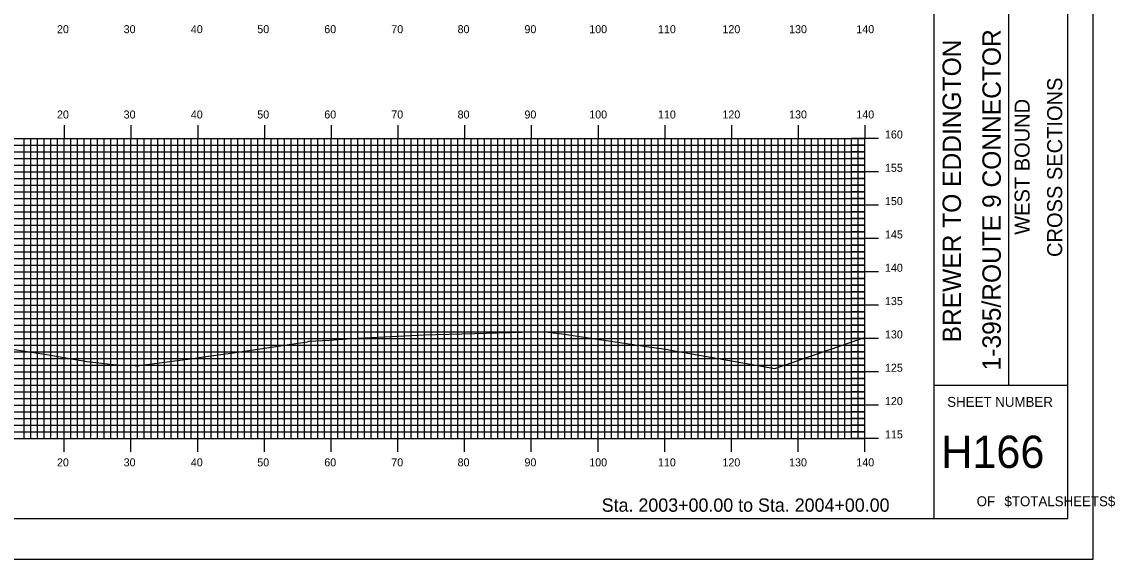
# Model space of a CAD drawing. Extents: x 851533 to 851876, y 366605 to 366825.
# Drawn here: x 851712.1 to 851875.9, y 366604.9 to 366685.6 of the extents above; entities that cross this region are included whole.
import ezdxf

# ---------------------------------------------------------------- set-up
doc = ezdxf.new("R2010")
doc.units = 0
for name, color, linetype in [('BORDER', 7, 'Continuous'), ('H_V ANNOTATION', 7, 'Continuous'), ('M_Roadway_Centerline', 7, 'Continuous'), ('MAJOR', 7, 'Continuous'), ('MINOR', 7, 'Continuous'), ('PLOT BOUNDARY', 7, 'Continuous'), ('S_Roadway_Centerline', 7, 'Continuous')]:
    doc.layers.add(name, color=color, linetype=linetype)

msp = doc.modelspace()

# ---------------------------------------------------------------- linework, layer by layer
at = {"layer": 'BORDER'}
for p, q in [((851848.85, 366611.06), (851848.85, 366821.06)), ((851860.03, 366631.06), (851860.03, 366701.06)), ((851848.85, 366631.06), (851868.85, 366631.06))]:
    msp.add_line(p, q, dxfattribs=at)
msp.add_lwpolyline([(851548.85, 366611.06), (851868.85, 366611.06), (851868.85, 366821.06), (851548.85, 366821.06)], close=True, dxfattribs=at)
at = {"layer": 'MAJOR'}
for p, q in [((851718.45, 366670.06), (851718.45, 366668.06)), ((851728.45, 366670.06), (851728.45, 366668.06)), ((851738.45, 366670.06), (851738.45, 366668.06)), ((851748.45, 366670.06), (851748.45, 366668.06)), ((851758.45, 366670.06), (851758.45, 366668.06)), ((851768.45, 366670.06), (851768.45, 366668.06)), ((851778.45, 366670.06), (851778.45, 366668.06)), ((851788.45, 366670.06), (851788.45, 366668.06)), ((851798.45, 366670.06), (851798.45, 366668.06)), ((851808.45, 366670.06), (851808.45, 366668.06)), ((851818.45, 366670.06), (851818.45, 366668.06)), ((851828.45, 366670.06), (851828.45, 366668.06)), ((851838.45, 366670.06), (851838.45, 366668.06)), ((851558.45, 366668.06), (851838.45, 366668.06)), ((851558.45, 366668.06), (851838.45, 366668.06)), ((851718.45, 366623.06), (851718.45, 366668.06)), ((851728.45, 366623.06), (851728.45, 366668.06)), ((851738.45, 366623.06), (851738.45, 366668.06)), ((851748.45, 366623.06), (851748.45, 366668.06)), ((851758.45, 366623.06), (851758.45, 366668.06)), ((851768.45, 366623.06), (851768.45, 366668.06)), ((851778.45, 366623.06), (851778.45, 366668.06)), ((851788.45, 366623.06), (851788.45, 366668.06)), ((851798.45, 366623.06), (851798.45, 366668.06)), ((851808.45, 366623.06), (851808.45, 366668.06)), ((851818.45, 366623.06), (851818.45, 366668.06)), ((851828.45, 366623.06), (851828.45, 366668.06)), ((851840.46, 366668.06), (851836.45, 366668.06)), ((851838.45, 366623.06), (851838.45, 366668.06)), ((851838.45, 366623.06), (851838.45, 366668.06)), ((851558.45, 366663.06), (851838.45, 366663.06)), ((851840.46, 366663.06), (851836.45, 366663.06)), ((851558.45, 366658.06), (851838.45, 366658.06)), ((851840.46, 366658.06), (851836.45, 366658.06)), ((851558.45, 366653.06), (851838.45, 366653.06)), ((851840.46, 366653.06), (851836.45, 366653.06)), ((851558.45, 366648.06), (851838.45, 366648.06)), ((851840.46, 366648.06), (851836.45, 366648.06)), ((851558.45, 366643.06), (851838.45, 366643.06)), ((851840.46, 366643.06), (851836.45, 366643.06)), ((851558.45, 366638.06), (851838.45, 366638.06)), ((851840.46, 366638.06), (851836.45, 366638.06)), ((851558.45, 366633.06), (851838.45, 366633.06)), ((851840.46, 366633.06), (851836.45, 366633.06)), ((851558.45, 366628.06), (851838.45, 366628.06)), ((851840.46, 366628.06), (851836.45, 366628.06)), ((851558.45, 366623.06), (851838.45, 366623.06)), ((851558.45, 366623.06), (851838.45, 366623.06)), ((851718.45, 366621.05), (851718.45, 366623.06)), ((851728.45, 366621.05), (851728.45, 366623.06)), ((851738.45, 366621.05), (851738.45, 366623.06)), ((851748.45, 366621.05), (851748.45, 366623.06)), ((851758.45, 366621.05), (851758.45, 366623.06)), ((851768.45, 366621.05), (851768.45, 366623.06)), ((851778.45, 366621.05), (851778.45, 366623.06)), ((851788.45, 366621.05), (851788.45, 366623.06)), ((851798.45, 366621.05), (851798.45, 366623.06)), ((851808.45, 366621.05), (851808.45, 366623.06)), ((851818.45, 366621.05), (851818.45, 366623.06)), ((851828.45, 366621.05), (851828.45, 366623.06)), ((851840.46, 366623.06), (851836.45, 366623.06)), ((851838.45, 366621.05), (851838.45, 366623.06))]:
    msp.add_line(p, q, dxfattribs=at)
at = {"layer": 'MINOR'}
for p, q in [((851558.45, 366667.06), (851838.45, 366667.06)), ((851712.45, 366623.06), (851712.45, 366668.06)), ((851713.45, 366623.06), (851713.45, 366668.06)), ((851714.45, 366623.06), (851714.45, 366668.06)), ((851715.45, 366623.06), (851715.45, 366668.06)), ((851716.45, 366623.06), (851716.45, 366668.06)), ((851717.45, 366623.06), (851717.45, 366668.06)), ((851719.45, 366623.06), (851719.45, 366668.06)), ((851720.45, 366623.06), (851720.45, 366668.06)), ((851721.45, 366623.06), (851721.45, 366668.06)), ((851722.45, 366623.06), (851722.45, 366668.06)), ((851723.45, 366623.06), (851723.45, 366668.06)), ((851724.45, 366623.06), (851724.45, 366668.06)), ((851725.45, 366623.06), (851725.45, 366668.06)), ((851726.45, 366623.06), (851726.45, 366668.06)), ((851727.45, 366623.06), (851727.45, 366668.06)), ((851729.45, 366623.06), (851729.45, 366668.06)), ((851730.45, 366623.06), (851730.45, 366668.06)), ((851731.45, 366623.06), (851731.45, 366668.06)), ((851732.45, 366623.06), (851732.45, 366668.06)), ((851733.45, 366623.06), (851733.45, 366668.06)), ((851734.45, 366623.06), (851734.45, 366668.06)), ((851735.45, 366623.06), (851735.45, 366668.06)), ((851736.45, 366623.06), (851736.45, 366668.06)), ((851737.45, 366623.06), (851737.45, 366668.06)), ((851739.45, 366623.06), (851739.45, 366668.06)), ((851740.45, 366623.06), (851740.45, 366668.06)), ((851741.45, 366623.06), (851741.45, 366668.06)), ((851742.45, 366623.06), (851742.45, 366668.06)), ((851743.45, 366623.06), (851743.45, 366668.06)), ((851744.45, 366623.06), (851744.45, 366668.06)), ((851745.45, 366623.06), (851745.45, 366668.06)), ((851746.45, 366623.06), (851746.45, 366668.06)), ((851747.45, 366623.06), (851747.45, 366668.06)), ((851749.45, 366623.06), (851749.45, 366668.06)), ((851750.45, 366623.06), (851750.45, 366668.06)), ((851751.45, 366623.06), (851751.45, 366668.06)), ((851752.45, 366623.06), (851752.45, 366668.06)), ((851753.45, 366623.06), (851753.45, 366668.06)), ((851754.45, 366623.06), (851754.45, 366668.06)), ((851755.45, 366623.06), (851755.45, 366668.06)), ((851756.45, 366623.06), (851756.45, 366668.06)), ((851757.45, 366623.06), (851757.45, 366668.06)), ((851759.45, 366623.06), (851759.45, 366668.06)), ((851760.45, 366623.06), (851760.45, 366668.06)), ((851761.45, 366623.06), (851761.45, 366668.06)), ((851762.45, 366623.06), (851762.45, 366668.06)), ((851763.45, 366623.06), (851763.45, 366668.06)), ((851764.45, 366623.06), (851764.45, 366668.06)), ((851765.45, 366623.06), (851765.45, 366668.06)), ((851766.45, 366623.06), (851766.45, 366668.06)), ((851767.45, 366623.06), (851767.45, 366668.06)), ((851769.45, 366623.06), (851769.45, 366668.06)), ((851770.45, 366623.06), (851770.45, 366668.06)), ((851771.45, 366623.06), (851771.45, 366668.06)), ((851772.45, 366623.06), (851772.45, 366668.06)), ((851773.45, 366623.06), (851773.45, 366668.06)), ((851774.45, 366623.06), (851774.45, 366668.06)), ((851775.45, 366623.06), (851775.45, 366668.06)), ((851776.45, 366623.06), (851776.45, 366668.06)), ((851777.45, 366623.06), (851777.45, 366668.06)), ((851779.45, 366623.06), (851779.45, 366668.06)), ((851780.45, 366623.06), (851780.45, 366668.06)), ((851781.45, 366623.06), (851781.45, 366668.06)), ((851782.45, 366623.06), (851782.45, 366668.06)), ((851783.45, 366623.06), (851783.45, 366668.06)), ((851784.45, 366623.06), (851784.45, 366668.06)), ((851785.45, 366623.06), (851785.45, 366668.06)), ((851786.45, 366623.06), (851786.45, 366668.06)), ((851787.45, 366623.06), (851787.45, 366668.06)), ((851789.45, 366623.06), (851789.45, 366668.06)), ((851790.45, 366623.06), (851790.45, 366668.06)), ((851791.45, 366623.06), (851791.45, 366668.06)), ((851792.45, 366623.06), (851792.45, 366668.06)), ((851793.45, 366623.06), (851793.45, 366668.06)), ((851794.45, 366623.06), (851794.45, 366668.06)), ((851795.45, 366623.06), (851795.45, 366668.06)), ((851796.45, 366623.06), (851796.45, 366668.06)), ((851797.45, 366623.06), (851797.45, 366668.06)), ((851799.45, 366623.06), (851799.45, 366668.06)), ((851800.45, 366623.06), (851800.45, 366668.06)), ((851801.45, 366623.06), (851801.45, 366668.06)), ((851802.45, 366623.06), (851802.45, 366668.06)), ((851803.45, 366623.06), (851803.45, 366668.06)), ((851804.45, 366623.06), (851804.45, 366668.06)), ((851805.45, 366623.06), (851805.45, 366668.06)), ((851806.45, 366623.06), (851806.45, 366668.06)), ((851807.45, 366623.06), (851807.45, 366668.06)), ((851809.45, 366623.06), (851809.45, 366668.06)), ((851810.45, 366623.06), (851810.45, 366668.06)), ((851811.45, 366623.06), (851811.45, 366668.06)), ((851812.45, 366623.06), (851812.45, 366668.06)), ((851813.45, 366623.06), (851813.45, 366668.06)), ((851814.45, 366623.06), (851814.45, 366668.06)), ((851815.45, 366623.06), (851815.45, 366668.06)), ((851816.45, 366623.06), (851816.45, 366668.06)), ((851817.45, 366623.06), (851817.45, 366668.06)), ((851819.45, 366623.06), (851819.45, 366668.06)), ((851820.45, 366623.06), (851820.45, 366668.06)), ((851821.45, 366623.06), (851821.45, 366668.06)), ((851822.45, 366623.06), (851822.45, 366668.06)), ((851823.45, 366623.06), (851823.45, 366668.06)), ((851824.45, 366623.06), (851824.45, 366668.06)), ((851825.45, 366623.06), (851825.45, 366668.06)), ((851826.45, 366623.06), (851826.45, 366668.06)), ((851827.45, 366623.06), (851827.45, 366668.06)), ((851829.45, 366623.06), (851829.45, 366668.06)), ((851830.45, 366623.06), (851830.45, 366668.06)), ((851831.45, 366623.06), (851831.45, 366668.06)), ((851832.45, 366623.06), (851832.45, 366668.06)), ((851833.45, 366623.06), (851833.45, 366668.06)), ((851834.45, 366623.06), (851834.45, 366668.06)), ((851835.45, 366623.06), (851835.45, 366668.06)), ((851836.45, 366623.06), (851836.45, 366668.06)), ((851838.45, 366667.06), (851836.45, 366667.06)), ((851837.45, 366623.06), (851837.45, 366668.06)), ((851558.45, 366666.06), (851838.45, 366666.06)), ((851838.45, 366666.06), (851836.45, 366666.06)), ((851558.45, 366665.06), (851838.45, 366665.06)), ((851558.45, 366664.06), (851838.45, 366664.06)), ((851838.45, 366665.06), (851836.45, 366665.06)), ((851838.45, 366664.06), (851836.45, 366664.06)), ((851558.45, 366662.06), (851838.45, 366662.06)), ((851838.45, 366662.06), (851836.45, 366662.06)), ((851558.45, 366661.06), (851838.45, 366661.06)), ((851838.45, 366661.06), (851836.45, 366661.06)), ((851558.45, 366660.06), (851838.45, 366660.06)), ((851558.45, 366659.06), (851838.45, 366659.06)), ((851838.45, 366660.06), (851836.45, 366660.06)), ((851838.45, 366659.06), (851836.45, 366659.06)), ((851558.45, 366657.06), (851838.45, 366657.06)), ((851838.45, 366657.06), (851836.45, 366657.06)), ((851558.45, 366656.06), (851838.45, 366656.06)), ((851838.45, 366656.06), (851836.45, 366656.06)), ((851558.45, 366655.06), (851838.45, 366655.06)), ((851558.45, 366654.06), (851838.45, 366654.06)), ((851838.45, 366655.06), (851836.45, 366655.06)), ((851838.45, 366654.06), (851836.45, 366654.06)), ((851558.45, 366652.06), (851838.45, 366652.06)), ((851558.45, 366651.06), (851838.45, 366651.06)), ((851838.45, 366652.06), (851836.45, 366652.06)), ((851838.45, 366651.06), (851836.45, 366651.06)), ((851558.45, 366650.06), (851838.45, 366650.06)), ((851558.45, 366649.06), (851838.45, 366649.06)), ((851838.45, 366650.06), (851836.45, 366650.06)), ((851838.45, 366649.06), (851836.45, 366649.06)), ((851558.45, 366647.06), (851838.45, 366647.06)), ((851558.45, 366646.06), (851838.45, 366646.06)), ((851838.45, 366647.06), (851836.45, 366647.06)), ((851838.45, 366646.06), (851836.45, 366646.06)), ((851558.45, 366645.06), (851838.45, 366645.06)), ((851558.45, 366644.06), (851838.45, 366644.06)), ((851838.45, 366645.06), (851836.45, 366645.06)), ((851838.45, 366644.06), (851836.45, 366644.06)), ((851558.45, 366642.06), (851838.45, 366642.06)), ((851558.45, 366641.06), (851838.45, 366641.06)), ((851838.45, 366642.06), (851836.45, 366642.06)), ((851838.45, 366641.06), (851836.45, 366641.06)), ((851558.45, 366640.06), (851838.45, 366640.06)), ((851558.45, 366639.06), (851838.45, 366639.06)), ((851838.45, 366640.06), (851836.45, 366640.06)), ((851838.45, 366639.06), (851836.45, 366639.06)), ((851558.45, 366637.06), (851838.45, 366637.06)), ((851558.45, 366636.06), (851838.45, 366636.06)), ((851838.45, 366637.06), (851836.45, 366637.06)), ((851838.45, 366636.06), (851836.45, 366636.06)), ((851558.45, 366635.06), (851838.45, 366635.06)), ((851838.45, 366635.06), (851836.45, 366635.06)), ((851558.45, 366634.06), (851838.45, 366634.06)), ((851838.45, 366634.06), (851836.45, 366634.06)), ((851558.45, 366632.06), (851838.45, 366632.06)), ((851558.45, 366631.06), (851838.45, 366631.06)), ((851838.45, 366632.06), (851836.45, 366632.06)), ((851838.45, 366631.06), (851836.45, 366631.06)), ((851558.45, 366630.06), (851838.45, 366630.06)), ((851838.45, 366630.06), (851836.45, 366630.06)), ((851558.45, 366629.06), (851838.45, 366629.06)), ((851838.45, 366629.06), (851836.45, 366629.06)), ((851558.45, 366627.06), (851838.45, 366627.06)), ((851558.45, 366626.06), (851838.45, 366626.06)), ((851838.45, 366627.06), (851836.45, 366627.06)), ((851838.45, 366626.06), (851836.45, 366626.06)), ((851558.45, 366625.06), (851838.45, 366625.06)), ((851838.45, 366625.06), (851836.45, 366625.06)), ((851558.45, 366624.06), (851838.45, 366624.06)), ((851838.45, 366624.06), (851836.45, 366624.06))]:
    msp.add_line(p, q, dxfattribs=at)
at = {"layer": 'PLOT BOUNDARY'}
msp.add_lwpolyline([(851532.66, 366604.94), (851872.66, 366604.94), (851872.66, 366824.94), (851532.66, 366824.94)], close=True, dxfattribs=at)
at = {"layer": 'S_Roadway_Centerline'}
msp.add_lwpolyline([(851704.04, 366637.43), (851715.83, 366635.65), (851721.85, 366634.61), (851726.75, 366634.05), (851728.81, 366634.04), (851729.31, 366633.96), (851736.94, 366634.95), (851737.76, 366635.03), (851739.33, 366635.28), (851744.12, 366635.94), (851754.87, 366637.56), (851755.13, 366637.66), (851758.13, 366637.81), (851761.56, 366638.03), (851768.28, 366638.38), (851770.38, 366638.52), (851772.27, 366638.58), (851779.92, 366638.82), (851788.79, 366639.04), (851790.97, 366638.98), (851793.41, 366638.68), (851796.02, 366638.32), (851805.36, 366636.92), (851808.59, 366636.44), (851809.89, 366636.22), (851812.21, 366635.8), (851824.96, 366633.55), (851837.4, 366637.84), (851838.45, 366638.19)], dxfattribs=at)

# ---------------------------------------------------------------- texts
at = {"layer": 'BORDER'}
for s, height, p in [('1-395/ROUTE 9 CONNECTOR', 2.7557, (851858.81, 366633.26)), ('BREWER TO EDDINGTON', 2.7557, (851852.84, 366637.46)), ('CROSS SECTIONS', 2.25, (851868.01, 366650.28)), ('WEST BOUND', 2.25, (851863.13, 366653.61))]:
    msp.add_text(s, height=height, rotation=90, dxfattribs=at).set_placement(p)
for s, height, p in [('SHEET NUMBER', 1.4905, (851850.78, 366627.79)), ('H166', 4.839, (851849.88, 366618.62)), ('$TOTALSHEETS$', 1.4905, (851859.36, 366612.88)), ('OF', 1.491, (851855.19, 366612.88))]:
    msp.add_text(s, height=height, dxfattribs=at).set_placement(p)
at = {"layer": 'H_V ANNOTATION'}
for s, height, p in [('20', 1.2, (851717.36, 366683.86)), ('30', 1.2, (851727.35, 366683.86)), ('40', 1.2, (851737.42, 366683.86)), ('50', 1.2, (851747.38, 366683.86)), ('60', 1.2, (851757.42, 366683.86)), ('70', 1.2, (851767.46, 366683.86)), ('80', 1.2, (851777.4, 366683.86)), ('90', 1.2, (851787.42, 366683.86)), ('100', 1.2, (851797.13, 366683.86)), ('110', 1.2, (851807.43, 366683.86)), ('120', 1.2, (851817.09, 366683.86)), ('130', 1.2, (851827.08, 366683.86)), ('140', 1.2, (851837.16, 366683.86)), ('20', 1.2, (851717.36, 366671.06)), ('30', 1.2, (851727.35, 366671.06)), ('40', 1.2, (851737.42, 366671.06)), ('50', 1.2, (851747.38, 366671.06)), ('60', 1.2, (851757.42, 366671.06)), ('70', 1.2, (851767.46, 366671.06)), ('80', 1.2, (851777.4, 366671.06)), ('90', 1.2, (851787.42, 366671.06)), ('100', 1.2, (851797.13, 366671.06)), ('110', 1.2, (851807.43, 366671.06)), ('120', 1.2, (851817.09, 366671.06)), ('130', 1.2, (851827.08, 366671.06)), ('140', 1.2, (851837.16, 366671.06)), ('160', 1.2, (851841.45, 366668.06)), ('155', 1.2, (851841.45, 366663.06)), ('150', 1.2, (851841.45, 366658.06)), ('145', 1.2, (851841.45, 366653.06)), ('140', 1.2, (851841.45, 366648.06)), ('135', 1.2, (851841.45, 366643.06)), ('130', 1.2, (851841.45, 366638.06)), ('125', 1.2, (851841.45, 366633.06)), ('120', 1.2, (851841.45, 366628.06)), ('115', 1.2, (851841.45, 366623.06)), ('20', 1.2, (851717.36, 366618.86)), ('30', 1.2, (851727.35, 366618.86)), ('40', 1.2, (851737.42, 366618.86)), ('50', 1.2, (851747.38, 366618.86)), ('60', 1.2, (851757.42, 366618.86)), ('70', 1.2, (851767.46, 366618.86)), ('80', 1.2, (851777.4, 366618.86)), ('90', 1.2, (851787.42, 366618.86)), ('100', 1.2, (851797.13, 366618.86)), ('110', 1.2, (851807.43, 366618.86)), ('120', 1.2, (851817.09, 366618.86)), ('130', 1.2, (851827.08, 366618.86)), ('140', 1.2, (851837.16, 366618.86)), ('Sta. 2003+00.00 to Sta. 2004+00.00', 2.0004, (851799, 366612.05))]:
    msp.add_text(s, height=height, dxfattribs=at).set_placement(p)
at = {"layer": 'M_Roadway_Centerline'}
for s, p in [('C', (851770.38, 366638.52)), ('L', (851770.38, 366638.51))]:
    msp.add_text(s, height=0.0146, dxfattribs=at).set_placement(p)

doc.saveas('drawing.dxf')
